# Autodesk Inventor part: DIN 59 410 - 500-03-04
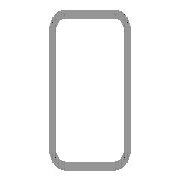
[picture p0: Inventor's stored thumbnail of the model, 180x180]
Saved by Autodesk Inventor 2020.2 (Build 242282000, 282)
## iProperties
Manager: www.cadconsulting.pl
Company: Fabian Stasiak CAD Consulting
Created: 2015-02
Part Number: DIN 59 410 - 500-03-04
Material: Stal
Description: Rurki stalowe o przekroju prostokątnym formowane na gorąco
Document SubType Name: Modellieren
Standard: DIN 59 410
Designer: F.Stasiak
Standards Organization: DIN
Language: pl-PL
Size Designation: 100x50x4.5-1680
Categories: <MemberInstance><Categories><Category DisplayName="Kształtowniki konstrukcyjne" InternalName="089c4875-fa83-4c05-b084-43b9cc11f5ed" Mnemonic="GRDR"><CategoryPar
Stock Number: 100x50x4.5
Density: 7.85 g/cm^3
Appearance: Płyta
Mass: 21668.7 g
Surface Area: 11135.3 cm^2
Volume: 2760.34 cm^3
IsCustomPart: 1
G_L: 1800,000 mm
Author: F.Stasiak
Subject: Zbiór ćwiczeń. Autodesk Inventor 2020. Kurs podstawowy
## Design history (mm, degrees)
node "Płaszczyzna początkowa"
node "Płaszczyzna końcowa"
sketch "Szkic1"
  geometry: L1 (-20, 60)-(20, 60); L2 (30, 50)-(30, -50); L3 (20, -60)-(-20, -60); L4 (-30, -50)-(-30, 50); L5 (-44.61, 0)-(44.61, 0) reference; L6 (0, -86.61)-(0, 86.61) reference; L7 (-20, 55)-(20, 55); L8 (25, 50)-(25, -50); L9 (20, -55)-(-20, -55); L10 (-25, -50)-(-25, 50); A1 r 10 centre (-20, 50) between (-20, 60) and (-30, 50); A2 r 10 centre (20, 50) between (30, 50) and (20, 60); A3 r 10 centre (20, -50) between (20, -60) and (30, -50); A4 r 10 centre (-20, -50) between (-30, -50) and (-20, -60); A5 r 5 centre (-20, 50) between (-20, 55) and (-25, 50); A6 r 5 centre (20, 50) between (25, 50) and (20, 55); A7 r 5 centre (20, -50) between (20, -55) and (25, -50); A8 r 5 centre (-20, -50) between (-25, -50) and (-20, -55); 3 further points
  constraints: 16 end point, 16 point on circle, 8 centre point, 8 tangent, 6 point on line, 4 parallel, 3 equal radius, 2 perpendicular, 1 horizontal, 7 other
  dimensions: "b" = 60 distance of point (-30, 60) point (30, 60); "ParH" = 120 distance of point (30, 60) point (30, -60); "msp_r" = 10 radius of A1 (= 2 x ParT); "d8" = 30 distance between parallel lines of L4 L6 (= 0.5 x b); "d9" = 60 distance between parallel lines of L5 L1 (= 0.5 x ParH); "d10" = 5 distance between parallel lines of L4 L10 (= ParT)
extrude "Bryła" new body sketch "Szkic1" taper "d4" = 0 deg; stored distance "NLG" = 10
node "Driven Length"
  sketch "Sketch2"
    geometry: L1 (0, 0)-(10, 0) reference
    constraints: 2 end point, 1 horizontal
  workplane "Work Plane3"
  sketch "Sketch3"
    geometry: L1 (-2, 0)-(12, 0) reference; L2 (-2, 1800)-(12, 1800) reference
    dimensions: "d14" = 1800 distance between parallel lines of L1 L2 (derived)
sketch "Szkic4"
  geometry: L1 (0, 100)-(0, 0) reference; L2 (1800, 100)-(1800, 0) reference; L3 (0, 50)-(1800, 50); 3 further points
  constraints: 2 end point, 2 midpoint, 2 point on line, 1 horizontal
  dimensions: "d15" = 60 distance from line of L1 point (60, 50); "d16" = 60 distance from line of L2 point (1740, 50)
hole "Otwór1" sketch "Szkic4" at (900, 50), (1740, 50), (60, 50) diameter "d17" = 50; stored, may be unused: countersink angle "d21" = 90 deg, drill point angle "d23" = 118 deg; dims "d18" = 6, "d19" = 4, "d20" = 2, "d22" = 8
sketch "Szkic5"
  geometry: L1 (0, 10)-(1800, 10) reference; L2 (0, -110)-(1800, -110) reference; L3 (63.629, 10)-(10, -35); L4 (10, -35)-(10, -65); L5 (10, -65)-(63.629, -110); L6 (0, 10)-(0, -110); C1 r 25 at (60, -50) reference; 1 further point
  constraints: 8 end point, 2 point on line, 1 equal length, 1 perpendicular, 1 vertical, 1 vertical alignment
  dimensions: "d24" = 50 distance from line of C1.centre L4; "d25" = 130 deg angle of L3 L4; "d26" = 30 distance of L3.end L4.end
extrude "Wyciągnięcie proste2" cut sketch "Szkic5" extent not by distance; stored distance "d27" = 10; taper "d28" = 0 deg
node "Płaszczyzna konstrukcyjna5"
  node "Oś konstrukcyjna1"
mirror "Odbicie lustrzane1"
body "Solid1"
other parameters: "ParT" = 5, "G_OFFSET_START" = 0 [user parameter; used in 1 equation term], "G_OFFSET_END" = 0 [user parameter; used in 1 equation term], "d11" = 0 (computed from G_OFFSET_START), "G_L" = 1800 (= d14) [user parameter], "d13" = 90 deg, "d29" = 0
